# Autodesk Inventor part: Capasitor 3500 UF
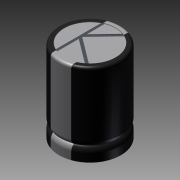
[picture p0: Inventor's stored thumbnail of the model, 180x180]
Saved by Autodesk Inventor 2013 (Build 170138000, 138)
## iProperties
Company: Autodesk Inc.
Created: 2005-12
Part Number: Capasitor 3500 UF
Document SubType Name: Modeling
Designer: Autodesk Inc.
Density: 1 g/cm^3
Mass: 1.78807 g
Surface Area: 8.36921 cm^2
Volume: 1.78807 cm^3
Material: Allgemein
Title: Personal Computer
Author: Autodesk Inc.
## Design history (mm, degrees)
sketch "Sketch1"
  geometry: L1 (0, 8.4)-(0, -8.4) reference; L2 (-8.4, 0)-(8.4, 0) reference; C1 r 6 at (0, 0)
  constraints: 2 midpoint, 1 centre point
  dimensions: "d0" = 12 diameter of C1
extrude "Extrusion1" new body sketch "Sketch1" distance "d1" = 16; taper "d2" = 0 deg
revolve "Revolution1" stored, may be unused: angle "d19" = 90 deg
sketch "Sketch2"
  geometry: C1 r 6 at (0, 0) reference; C2 r 5 at (0, 0)
  constraints: 1 centre point, 1 coincident
  dimensions: "d3" = 1 radial gap between concentric circles of C2 C1
extrude "Extrusion2" cut sketch "Sketch2" distance "d4" = 0.1; taper "d5" = 0 deg
sketch "Sketch3"
  geometry: L1 (-2.278, 4.663)-(-1.805, 4.663); L2 (-1.805, 4.663)-(-1.805, -4.942); L3 (-1.805, -4.942)-(-2.278, -4.942); L4 (-2.278, -4.942)-(-2.278, 4.663); L5 (-1.805, 0.278)-(-2.233, 0.684); L6 (-2.233, 0.684)-(1.932, 5.071); L7 (1.932, 5.071)-(2.36, 4.665); L8 (2.36, 4.665)-(-1.805, 0.278); L9 (-1.805, 0.278)-(-2.119, -0.141); L10 (-2.119, -0.141)-(3.111, -4.062); L11 (3.111, -4.062)-(3.425, -3.643); L12 (3.425, -3.643)-(-1.805, 0.278); A1 r 5 centre (0, 0) between (-1.805, 4.663) and (3.425, -3.643) reference
  constraints: 24 end point, 6 parallel, 3 perpendicular, 2 point on circle, 1 horizontal, 1 point on line
extrude "Extrusion3" cut sketch "Sketch3" distance "d6" = 0.05; taper "d7" = 0 deg
fillet "Fillet1" dims "d8" = 0.5
sketch "Sketch5"
  geometry: L1 (2, -4.583)-(2, -7); L2 (2, -7)-(-2, -7); L3 (-2, -7)-(-2, -4.583); L4 (0, -9.6)-(0, 8.6) reference; A1 r 5 centre (0, 0) between (-2, -4.583) and (2, -4.583) reference; 3 further points
  constraints: 6 end point, 2 point on circle, 1 coincident, 1 parallel, 1 point on line, 1 vertical alignment, 2 other
  dimensions: "d12" = 1 distance from line of L2 point (0, -6); "d13" = 4 distance of L1.end L2.end
split "Split1" sketch "Sketch5"
workplane "Work Plane1"
body "Solid1"
sketch "Sketch6"
  geometry: L1 (0, 19.2)-(0, -3.2) reference; L2 (6, 0)-(6, 16) reference; L3 (6, 3.5)-(6, 1.5); L4 (6, 2.5)-(5.5, 2.5); L5 (-6, 0)-(6, 0) reference; A1 r 1.25 centre (4.75, 3.5) between (5.5, 2.5) and (6, 3.5); A2 r 1.25 centre (4.75, 1.5) between (6, 1.5) and (5.5, 2.5); 1 further point
  constraints: 4 end point, 4 point on circle, 2 centre point, 2 point on line, 2 tangent, 1 collinear, 1 horizontal, 1 midpoint
  dimensions: "d16" = 2 distance of L3.start L3.end; "d17" = 2.5 distance between parallel lines of L5 L4; "d18" = 0.5 distance of L4.start L4.end
